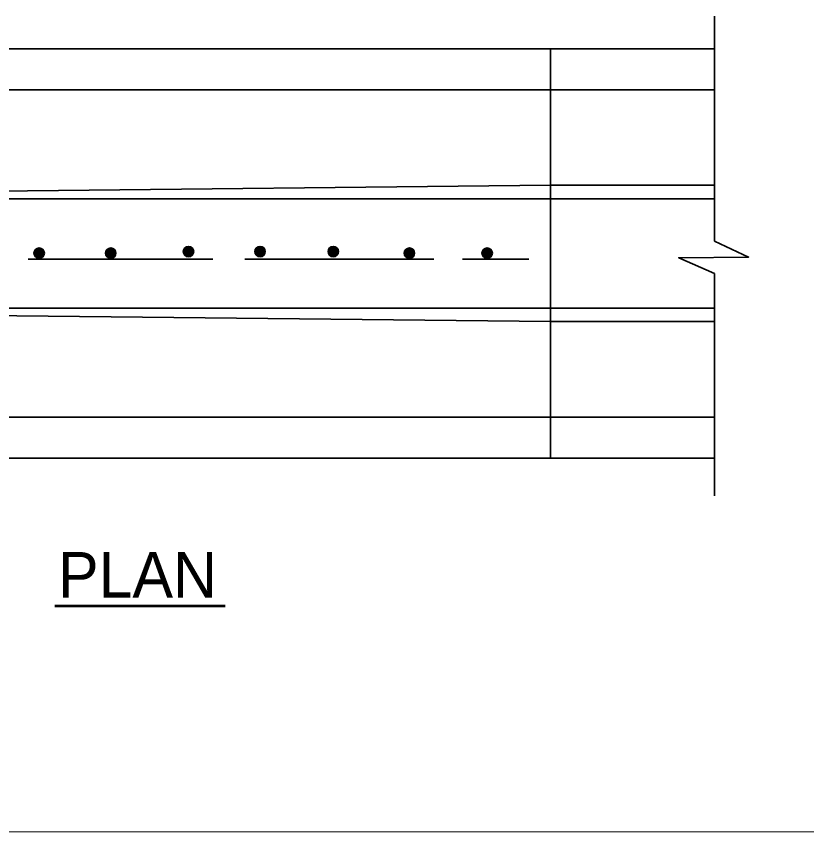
# Model space of a CAD drawing. Extents: x -11.7 to -4.5, y 8.6 to 18.8.
# Drawn here: x -7.133 to -5.379, y 16.995 to 18.788 of the extents above; entities that cross this region are included whole.
import ezdxf
from ezdxf.enums import TextEntityAlignment as Align

# ---------------------------------------------------------------- set-up
doc = ezdxf.new("R2010")
doc.units = 0
doc.header["$LTSCALE"] = 0.024
for name, color, linetype, lineweight in [('1', 7, 'Continuous', 35), ('10', 7, 'Continuous', 13), ('12', 7, 'Continuous', 53)]:
    doc.layers.add(name, color=color, linetype=linetype, lineweight=lineweight)

msp = doc.modelspace()

# ---------------------------------------------------------------- linework, layer by layer
at = {"layer": '1'}
for p, q in [((-7.99983, 18.7165), (-5.59767, 18.7165)), ((-5.95783, 18.7165), (-5.95783, 17.81633)), ((-5.95783, 18.4165), (-8.71983, 18.3865)), ((-5.59933, 18.4165), (-5.95783, 18.4165)), ((-8.71983, 18.3865), (-5.95783, 18.3865)), ((-5.59933, 18.3865), (-5.95783, 18.3865)), ((-7.10633, 18.2535), (-6.70083, 18.2535)), ((-6.6305, 18.2535), (-6.21483, 18.2535)), ((-6.00533, 18.2535), (-6.15117, 18.2535)), ((-8.71983, 18.14633), (-5.95783, 18.14633)), ((-5.59933, 18.14633), (-5.95783, 18.14633)), ((-8.71983, 17.90633), (-5.59933, 17.90633)), ((-7.99983, 17.81633), (-5.59767, 17.81633))]:
    msp.add_line(p, q, dxfattribs=at)
for points in [[(-8.71983, 17.90633), (-8.71983, 18.6265), (-5.59933, 18.6265)], [(-5.59933, 18.11633), (-5.95783, 18.11633), (-8.71983, 18.14633)]]:
    msp.add_lwpolyline(points, dxfattribs=at)
for centre, radius in [((-7.08252, 18.26701), 0.01145), ((-7.08262, 18.2671), 0.01068), ((-7.08365, 18.2671), 0.00926), ((-7.0825, 18.26683), 0.0103), ((-7.08219, 18.26635), 0.0101), ((-7.08224, 18.26671), 0.0094), ((-7.08327, 18.26755), 0.00766), ((-7.08199, 18.26665), 0.0089), ((-7.08192, 18.2664), 0.00843), ((-7.08345, 18.26665), 0.00665), ((-7.08179, 18.26628), 0.00805), ((-7.08192, 18.26608), 0.00767), ((-7.08172, 18.26608), 0.00747), ((-7.08187, 18.2662), 0.00722), ((-7.08154, 18.26602), 0.0069), ((-7.08147, 18.26615), 0.00646), ((-6.92502, 18.26701), 0.01145), ((-6.92512, 18.2671), 0.01068), ((-6.92614, 18.2671), 0.00926), ((-6.92499, 18.26683), 0.0103), ((-6.92468, 18.26635), 0.0101), ((-6.92474, 18.26671), 0.0094), ((-6.92577, 18.26755), 0.00766), ((-6.92449, 18.26665), 0.0089), ((-6.92441, 18.2664), 0.00843), ((-6.92595, 18.26665), 0.00665), ((-6.92429, 18.26628), 0.00805), ((-6.92441, 18.26608), 0.00767), ((-6.92422, 18.26608), 0.00747), ((-6.92436, 18.2662), 0.00722), ((-6.92404, 18.26602), 0.0069), ((-6.92396, 18.26615), 0.00646), ((-6.75411, 18.27037), 0.01145), ((-6.75421, 18.27046), 0.01068), ((-6.75524, 18.27046), 0.00926), ((-6.75408, 18.27019), 0.0103), ((-6.75378, 18.26971), 0.0101), ((-6.75383, 18.27007), 0.0094), ((-6.75486, 18.27091), 0.00766), ((-6.75358, 18.27001), 0.0089), ((-6.75351, 18.26976), 0.00843), ((-6.75504, 18.27001), 0.00665), ((-6.75338, 18.26964), 0.00805), ((-6.75351, 18.26944), 0.00767), ((-6.75561, 18.26964), 0.00531), ((-6.75331, 18.26944), 0.00747), ((-6.75345, 18.26956), 0.00722), ((-6.75313, 18.26938), 0.0069), ((-6.75306, 18.26951), 0.00646), ((-6.75473, 18.26989), 0.00429), ((-6.753, 18.26958), 0.00601), ((-6.753, 18.26971), 0.00551), ((-6.75293, 18.26956), 0.00519), ((-6.75293, 18.26951), 0.00468), ((-6.75273, 18.26911), 0.00448), ((-6.75263, 18.26906), 0.00409), ((-6.75263, 18.26917), 0.00359), ((-6.75248, 18.26926), 0.00346), ((-6.59661, 18.27037), 0.01145), ((-6.5967, 18.27046), 0.01068), ((-6.59773, 18.27046), 0.00926), ((-6.59658, 18.27019), 0.0103), ((-6.59627, 18.26971), 0.0101), ((-6.59633, 18.27007), 0.0094), ((-6.59735, 18.27091), 0.00766), ((-6.59607, 18.27001), 0.0089), ((-6.596, 18.26976), 0.00843), ((-6.59753, 18.27001), 0.00665), ((-6.59588, 18.26964), 0.00805), ((-6.596, 18.26944), 0.00767), ((-6.59811, 18.26964), 0.00531), ((-6.5958, 18.26944), 0.00747), ((-6.59595, 18.26956), 0.00722), ((-6.59562, 18.26938), 0.0069), ((-6.59555, 18.26951), 0.00646), ((-6.59723, 18.26989), 0.00429), ((-6.5955, 18.26958), 0.00601), ((-6.5955, 18.26971), 0.00551), ((-6.59543, 18.26956), 0.00519), ((-6.59543, 18.26951), 0.00468), ((-6.59523, 18.26911), 0.00448), ((-6.59512, 18.26906), 0.00409), ((-6.59512, 18.26917), 0.00359), ((-6.59498, 18.26926), 0.00346), ((-6.43574, 18.27037), 0.01145), ((-6.43584, 18.27046), 0.01068), ((-6.43686, 18.27046), 0.00926), ((-6.43571, 18.27019), 0.0103), ((-6.43541, 18.26971), 0.0101), ((-6.43546, 18.27007), 0.0094), ((-6.43649, 18.27091), 0.00766), ((-6.43521, 18.27001), 0.0089), ((-6.43514, 18.26976), 0.00843), ((-6.43667, 18.27001), 0.00665), ((-6.43501, 18.26964), 0.00805), ((-6.43514, 18.26944), 0.00767), ((-6.43724, 18.26964), 0.00531), ((-6.43494, 18.26944), 0.00747), ((-6.43508, 18.26956), 0.00722), ((-6.43476, 18.26938), 0.0069), ((-6.43469, 18.26951), 0.00646), ((-6.43636, 18.26989), 0.00429), ((-6.43463, 18.26958), 0.00601), ((-6.43463, 18.26971), 0.00551), ((-6.43456, 18.26956), 0.00519), ((-6.43456, 18.26951), 0.00468), ((-6.43436, 18.26911), 0.00448), ((-6.43425, 18.26906), 0.00409), ((-6.43425, 18.26917), 0.00359), ((-6.43411, 18.26926), 0.00346), ((-6.26819, 18.26701), 0.01145), ((-6.26829, 18.2671), 0.01068), ((-6.26932, 18.2671), 0.00926), ((-6.26817, 18.26683), 0.0103), ((-6.26786, 18.26635), 0.0101), ((-6.26791, 18.26671), 0.0094), ((-6.26894, 18.26755), 0.00766), ((-6.26766, 18.26665), 0.0089), ((-6.26759, 18.2664), 0.00843), ((-6.26912, 18.26665), 0.00665), ((-6.26746, 18.26628), 0.00805), ((-6.26759, 18.26608), 0.00767), ((-6.26739, 18.26608), 0.00747), ((-6.26754, 18.2662), 0.00722), ((-6.26721, 18.26602), 0.0069), ((-6.26714, 18.26615), 0.00646), ((-6.09729, 18.26701), 0.01145), ((-6.09738, 18.2671), 0.01068), ((-6.09841, 18.2671), 0.00926), ((-6.09726, 18.26683), 0.0103), ((-6.09695, 18.26635), 0.0101), ((-6.09701, 18.26671), 0.0094), ((-6.09803, 18.26755), 0.00766), ((-6.09675, 18.26665), 0.0089), ((-6.09668, 18.2664), 0.00843), ((-6.09821, 18.26665), 0.00665), ((-6.09656, 18.26628), 0.00805), ((-6.09668, 18.26608), 0.00767), ((-6.09648, 18.26608), 0.00747), ((-6.09663, 18.2662), 0.00722), ((-6.0963, 18.26602), 0.0069), ((-6.09623, 18.26615), 0.00646), ((-7.08403, 18.26628), 0.00531), ((-7.08142, 18.26622), 0.00601), ((-7.08314, 18.26653), 0.00429), ((-7.08142, 18.26635), 0.00551), ((-7.08134, 18.2662), 0.00519), ((-7.08134, 18.26615), 0.00468), ((-7.08115, 18.26575), 0.00448), ((-7.08104, 18.2657), 0.00409), ((-7.08104, 18.26581), 0.00359), ((-7.08089, 18.2659), 0.00346), ((-7.08089, 18.26557), 0.00319), ((-7.08077, 18.26583), 0.00306), ((-7.08071, 18.26575), 0.00262), ((-7.08089, 18.26595), 0.00218), ((-7.08064, 18.26568), 0.00194), ((-7.08057, 18.2657), 0.00161), ((-7.08044, 18.26563), 0.00122), ((-7.08044, 18.26575), 0.00108), ((-7.08007, 18.2657), 0.00136), ((-7.08046, 18.26575), 0.000706), ((-7.08059, 18.26575), 0.000332), ((-7.08032, 18.26575), 0.000211), ((-6.92652, 18.26628), 0.00531), ((-6.92564, 18.26653), 0.00429), ((-6.92391, 18.26622), 0.00601), ((-6.92391, 18.26635), 0.00551), ((-6.92384, 18.2662), 0.00519), ((-6.92384, 18.26615), 0.00468), ((-6.92364, 18.26575), 0.00448), ((-6.92353, 18.2657), 0.00409), ((-6.92353, 18.26581), 0.00359), ((-6.92339, 18.2659), 0.00346), ((-6.92339, 18.26557), 0.00319), ((-6.92326, 18.26583), 0.00306), ((-6.92321, 18.26575), 0.00262), ((-6.92339, 18.26595), 0.00218), ((-6.92314, 18.26568), 0.00194), ((-6.92306, 18.2657), 0.00161), ((-6.92294, 18.26563), 0.00122), ((-6.92294, 18.26575), 0.00108), ((-6.92256, 18.2657), 0.00136), ((-6.92296, 18.26575), 0.000706), ((-6.92308, 18.26575), 0.000332), ((-6.92281, 18.26575), 0.000211), ((-6.75248, 18.26893), 0.00319), ((-6.75236, 18.26919), 0.00306), ((-6.7523, 18.26911), 0.00262), ((-6.75248, 18.26931), 0.00218), ((-6.75223, 18.26904), 0.00194), ((-6.75216, 18.26906), 0.00161), ((-6.75203, 18.26899), 0.00122), ((-6.75203, 18.26911), 0.00108), ((-6.75165, 18.26906), 0.00136), ((-6.75205, 18.26911), 0.000706), ((-6.75218, 18.26911), 0.000332), ((-6.75191, 18.26911), 0.000211), ((-6.59498, 18.26893), 0.00319), ((-6.59485, 18.26919), 0.00306), ((-6.5948, 18.26911), 0.00262), ((-6.59498, 18.26931), 0.00218), ((-6.59472, 18.26904), 0.00194), ((-6.59465, 18.26906), 0.00161), ((-6.59453, 18.26899), 0.00122), ((-6.59453, 18.26911), 0.00108), ((-6.59415, 18.26906), 0.00136), ((-6.59454, 18.26911), 0.000706), ((-6.59467, 18.26911), 0.000332), ((-6.5944, 18.26911), 0.000211), ((-6.43411, 18.26893), 0.00319), ((-6.43398, 18.26919), 0.00306), ((-6.43393, 18.26911), 0.00262), ((-6.43411, 18.26931), 0.00218), ((-6.43386, 18.26904), 0.00194), ((-6.43379, 18.26906), 0.00161), ((-6.43366, 18.26899), 0.00122), ((-6.43366, 18.26911), 0.00108), ((-6.43328, 18.26906), 0.00136), ((-6.43368, 18.26911), 0.000706), ((-6.4338, 18.26911), 0.000332), ((-6.43353, 18.26911), 0.000211), ((-6.2697, 18.26628), 0.00531), ((-6.26709, 18.26622), 0.00601), ((-6.26881, 18.26653), 0.00429), ((-6.26709, 18.26635), 0.00551), ((-6.26701, 18.2662), 0.00519), ((-6.26701, 18.26615), 0.00468), ((-6.26682, 18.26575), 0.00448), ((-6.26671, 18.2657), 0.00409), ((-6.26671, 18.26581), 0.00359), ((-6.26656, 18.2659), 0.00346), ((-6.26656, 18.26557), 0.00319), ((-6.26644, 18.26583), 0.00306), ((-6.26638, 18.26575), 0.00262), ((-6.26656, 18.26595), 0.00218), ((-6.26631, 18.26568), 0.00194), ((-6.26624, 18.2657), 0.00161), ((-6.26611, 18.26563), 0.00122), ((-6.26611, 18.26575), 0.00108), ((-6.26574, 18.2657), 0.00136), ((-6.26613, 18.26575), 0.000706), ((-6.26626, 18.26575), 0.000332), ((-6.26599, 18.26575), 0.000211), ((-6.09879, 18.26628), 0.00531), ((-6.09791, 18.26653), 0.00429), ((-6.09618, 18.26622), 0.00601), ((-6.09618, 18.26635), 0.00551), ((-6.09611, 18.2662), 0.00519), ((-6.09611, 18.26615), 0.00468), ((-6.09591, 18.26575), 0.00448), ((-6.0958, 18.2657), 0.00409), ((-6.0958, 18.26581), 0.00359), ((-6.09566, 18.2659), 0.00346), ((-6.09566, 18.26557), 0.00319), ((-6.09553, 18.26583), 0.00306), ((-6.09548, 18.26575), 0.00262), ((-6.09566, 18.26595), 0.00218), ((-6.0954, 18.26568), 0.00194), ((-6.09533, 18.2657), 0.00161), ((-6.09521, 18.26563), 0.00122), ((-6.09521, 18.26575), 0.00108), ((-6.09483, 18.2657), 0.00136), ((-6.09522, 18.26575), 0.000706), ((-6.09535, 18.26575), 0.000332), ((-6.09508, 18.26575), 0.000211)]:
    msp.add_circle(centre, radius, dxfattribs=at)
at = {"layer": '10', "lineweight": 35}
for p, q in [((-5.59767, 18.78783), (-5.59767, 18.29367)), ((-5.59767, 17.733), (-5.59767, 18.22233))]:
    msp.add_line(p, q, dxfattribs=at)
at = {"layer": '10'}
msp.add_line((-5.37917, 16.99467), (-10.32767, 16.99467), dxfattribs=at)
at = {"layer": '10', "lineweight": 35}
msp.add_lwpolyline([(-5.59733, 18.2225), (-5.67583, 18.25683), (-5.5225, 18.25817), (-5.59733, 18.29367)], dxfattribs=at)
at = {"layer": '12'}
msp.add_line((-7.04833, 17.49117), (-6.6735, 17.49117), dxfattribs=at)

# ---------------------------------------------------------------- texts
msp.add_text('PLAN', height=0.1, dxfattribs=at).set_placement((-6.86625, 17.50967), align=Align.CENTER)

doc.saveas('drawing.dxf')
